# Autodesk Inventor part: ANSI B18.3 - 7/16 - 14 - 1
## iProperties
Comments: To add or edit properties for Autodesk Inventor files, use iProperties.
Created: 2005-05
Part Number: ANSI B18.3 - 7/16 - 14 - 1
Vendor: Autodesk Inc.
Document SubType Name: Modeling
Designer: John Blackburn
Material: Default
Description: Hexagon Socket Head Cap Screw
Standard: ANSI B18.3
Alert: To add or edit properties for Autodesk Inventor files, use iProperties.
Control State: 0
Master: False
Checked Out: False
Shininess: 64.0
Length Units: 11272
Angle Units: 11279
Time Units: 11290
Mass Units: 11286
Length Display Precision: 3
Angle Display Precision: 2
Compacted: True
EGR: 3
Classification: un/spsc 31161501
Density: 0.0
Volumn: 0.0
Area: 0.0
PropertySet Name: Model Information
Author: John Blackburn
Revision Number: 8
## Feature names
1. Body [Revolution]
2. Slot [Extrusion]
3. Fillet1
4. Chamfer1
